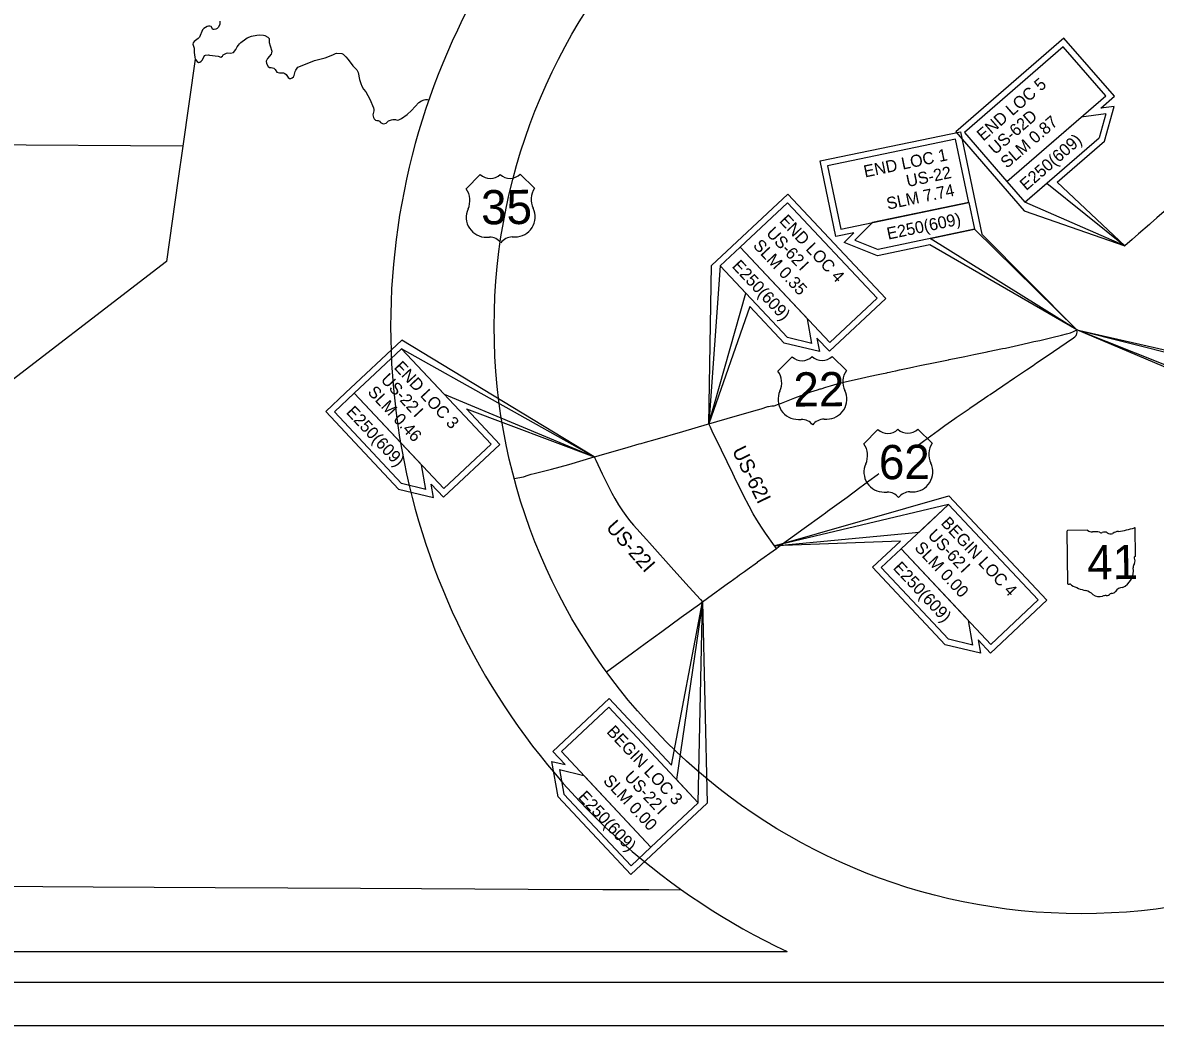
# Model space of a CAD drawing. Extents: x 86259 to 205259, y 423331 to 500331.
# Drawn here: x 126607 to 172720, y 423331 to 464136 of the extents above; entities that cross this region are included whole.
import ezdxf

# ---------------------------------------------------------------- set-up
doc = ezdxf.new("R2010")
doc.units = 0
for name, color, linetype in [('Default', 7, 'Continuous'), ('MT_X_Cells', 7, 'Continuous'), ('PM_P_Cells', 7, 'Continuous'), ('PM_X_Cells', 7, 'Continuous'), ('SC_Scratch1', 7, 'Continuous'), ('SH_Border', 7, 'Continuous'), ('SH_Cut_Line', 7, 'Continuous'), ('SH_Data', 7, 'Continuous'), ('SN_P_Signs', 7, 'Continuous'), ('XS_P_Annotation', 7, 'Continuous')]:
    doc.layers.add(name, color=color, linetype=linetype)

msp = doc.modelspace()

# ---------------------------------------------------------------- linework, layer by layer
at = {"layer": 'MT_X_Cells'}
msp.add_line((146621, 445580), (146999, 445652), dxfattribs=at)
at = {"layer": 'PM_P_Cells'}
for points in [[(174416, 457630), (173884, 457161), (173467, 456791), (173222, 456574), (172987, 456373), (172774, 456190), (172520, 455957), (172483, 455922), (172034, 455537), (171782, 455312), (171481, 455055)], [(166622, 450896), (167153, 451014), (167556, 451104), (167663, 451128), (167776, 451154), (168014, 451208), (168511, 451323), (168904, 451414), (169107, 451473), (169260, 451517), (169383, 451563), (169524, 451634)], [(167478, 450009), (167740, 450187), (167886, 450287), (168311, 450575), (169083, 451105), (169386, 451314), (169443, 451357), (169491, 451399), (169515, 451441), (169525, 451476), (169534, 451549), (169524, 451634)], [(162010, 449940), (162158, 449972), (162304, 450003), (162504, 450047), (162710, 450091), (162890, 450130), (163127, 450179), (163755, 450310), (164296, 450420), (164332, 450428), (164957, 450555), (165327, 450630), (165868, 450741), (165916, 450750), (166497, 450869), (166622, 450896)], [(158697, 449107), (158971, 449197), (159072, 449229), (159110, 449241), (159306, 449299), (159488, 449352), (159770, 449434), (160150, 449531), (160579, 449630), (161105, 449746), (161429, 449817), (161644, 449864)], [(161644, 449864), (161721, 449878)], [(161721, 449878), (161785, 449891), (161818, 449898), (161890, 449914)], [(161890, 449914), (162010, 449940)], [(165770, 448853), (165903, 448944), (165991, 449003), (166517, 449356), (166992, 449679), (167478, 450009)], [(157197, 448545), (157374, 448614), (157494, 448656), (158048, 448874), (158553, 449059), (158697, 449107)], [(162963, 446872), (163283, 447100), (163878, 447538), (164156, 447736), (164561, 448024), (164616, 448061), (165134, 448417), (165171, 448442), (165770, 448853)], [(146999, 445652), (147189, 445726), (147302, 445760), (147434, 445793), (147753, 445865), (148136, 445962), (148848, 446161), (149877, 446461), (149948, 446481), (150078, 446519), (151262, 446862), (151709, 446990), (151783, 447011), (151960, 447062), (152352, 447173), (153488, 447504), (154485, 447791), (154545, 447809), (155619, 448119), (156519, 448378), (156674, 448427), (156937, 448511), (156976, 448522), (157035, 448532), (157103, 448539), (157197, 448545)], [(157297, 442742), (157220, 442848), (156846, 443365), (156682, 443609), (156497, 443899), (156347, 444153), (156181, 444454), (155958, 444892), (155591, 445641), (155520, 445786), (154823, 447212), (154710, 447449), (154603, 447677), (154569, 447750), (154545, 447809)], [(149877, 446461), (149908, 446390), (149939, 446325), (150197, 445778), (150414, 445336), (150593, 444987), (150712, 444772), (150864, 444520), (151025, 444273), (151167, 444073), (151317, 443879), (151475, 443691), (152000, 443097), (152123, 442961), (153117, 441861), (153743, 441168), (154203, 440655), (154284, 440566)], [(160691, 445219), (160834, 445326), (161062, 445492), (161401, 445739), (161461, 445782)], [(159139, 444076), (159285, 444182), (159379, 444251), (159852, 444599), (160169, 444830), (160691, 445219)], [(156526, 442189), (157297, 442742), (157396, 442814), (158428, 443560), (159139, 444076)], [(155704, 441598), (155788, 441659), (155995, 441807), (156099, 441883), (156522, 442186), (156526, 442189)], [(154155, 440473), (154284, 440566), (154494, 440718), (155344, 441339)], [(155344, 441339), (155407, 441384), (155704, 441598)], [(150373, 437719), (151436, 438493), (151950, 438871), (152626, 439361), (153420, 439940), (154155, 440473)]]:
    msp.add_lwpolyline(points, dxfattribs=at)
at = {"layer": 'PM_X_Cells'}
for points in [[(134628, 464197), (134638, 464131), (134632, 464079), (134583, 463955), (134519, 463905), (134469, 463877), (134401, 463859), (134351, 463863), (134277, 463976), (134221, 463990), (134171, 463996), (134117, 463980), (134044, 463944), (133986, 463900), (133932, 463843), (133803, 463550), (133746, 463486), (133588, 463369), (133551, 463317), (133541, 463263), (133587, 463092), (133594, 462978), (133590, 462922), (133612, 462734), (133632, 462657), (133130, 459110), (124610, 459164)], [(133632, 462657), (133709, 462549), (133765, 462517), (133822, 462525), (133876, 462567), (133926, 462618), (134003, 462795), (134055, 462816), (134167, 462826), (134219, 462812), (134568, 462767), (134676, 462736), (134740, 462772), (134774, 462824), (134907, 462898), (134957, 462908), (135063, 462891), (135193, 462923), (135290, 463041), (135344, 463153), (135391, 463221), (135433, 463279), (135483, 463323), (135686, 463478), (135746, 463512), (135919, 463584), (136139, 463633), (136264, 463643), (136406, 463628), (136464, 463612), (136586, 463544), (136636, 463491), (136649, 463323), (136677, 463197), (136745, 462980), (136742, 462912), (136722, 462852), (136577, 462678), (136543, 462626), (136525, 462570), (136539, 462470), (136602, 462358), (136656, 462317), (136721, 462313), (136837, 462279), (136889, 462230), (136950, 462122), (137006, 462102), (137067, 462092), (137121, 462095), (137171, 462099), (137227, 462089), (137279, 462069), (137335, 462023), (137419, 461904), (137473, 461868), (137523, 461870), (137579, 461890), (137629, 461934), (137661, 461988), (137700, 462150), (137726, 462208), (137815, 462324), (138324, 462532), (138491, 462592), (138920, 462707), (139233, 462828), (139337, 462878), (139388, 462892), (139598, 462875), (139652, 462851), (139764, 462752), (139860, 462640), (140053, 462375), (140205, 462210), (140241, 462156), (140263, 462106), (140320, 461823), (140372, 461663), (140420, 461546), (140487, 461436), (140573, 461321), (140741, 461018), (140888, 460665), (140904, 460605), (140903, 460553), (140867, 460391), (140873, 460333), (140889, 460281), (140916, 460228), (140970, 460174), (141024, 460158), (141083, 460156), (141135, 460131), (141175, 460075), (141231, 460041), (141289, 460025), (141345, 460027), (141405, 460046), (141507, 460138), (141618, 460182), (141676, 460190), (141780, 460190), (141848, 460163), (141920, 460185), (142027, 460235), (142264, 460404), (142432, 460556), (142736, 460884), (142842, 460956), (142957, 460997), (143009, 461005), (143069, 461003), (143139, 460982)], [(133130, 459110), (132930, 457697), (132466, 454415), (124754, 448504)], [(153447, 428834), (152105, 428841), (150230, 428850), (147184, 428866), (142841, 428889), (140363, 428903), (134438, 428933), (129473, 428959), (123335, 428991)]]:
    msp.add_lwpolyline(points, dxfattribs=at)
at = {"layer": 'SC_Scratch1'}
for p, q in [((168995, 463509), (164592, 459687)), ((171053, 461138), (168995, 463509)), ((170494, 460652), (171053, 461138)), ((171047, 460727), (170494, 460652)), ((170648, 459313), (171047, 460727)), ((159075, 458507), (164782, 459696)), ((164592, 459687), (167380, 456476)), ((164782, 459696), (165650, 455533)), ((168729, 457647), (170648, 459313)), ((159715, 455433), (159075, 458507)), ((171481, 455055), (168729, 457647)), ((154652, 454255), (157755, 457163)), ((157755, 457163), (161742, 452910)), ((167380, 456476), (171481, 455055)), ((160440, 455584), (159715, 455433)), ((160046, 455189), (160440, 455584)), ((161412, 454650), (160046, 455189)), ((165650, 455533), (169524, 451634)), ((163540, 455093), (161412, 454650)), ((169524, 451634), (163540, 455093)), ((154545, 447809), (154652, 454255)), ((161742, 452910), (159451, 450763)), ((156215, 452588), (154545, 447809)), ((157613, 451097), (156215, 452588)), ((169524, 451634), (177634, 449784)), ((177634, 448192), (169524, 451634)), ((142045, 451220), (139755, 449073)), ((149877, 446461), (142045, 451220)), ((159041, 450753), (157613, 451097)), ((159451, 450763), (158945, 451303)), ((158945, 451303), (159041, 450753)), ((139755, 449073), (138943, 448312)), ((138943, 448312), (141903, 445154)), ((146033, 446967), (144671, 448420)), ((144671, 448420), (149877, 446461)), ((143742, 444820), (146033, 446967)), ((141903, 445154), (143331, 444810)), ((143331, 444810), (143236, 445360)), ((143236, 445360), (143742, 444820)), ((157220, 442848), (164311, 444883)), ((164311, 444883), (168298, 440630)), ((162342, 443038), (157220, 442848)), ((161208, 441975), (162342, 443038)), ((164169, 438817), (161208, 441975)), ((153023, 433916), (154284, 440566)), ((154284, 440566), (154467, 432376)), ((168298, 440630), (166007, 438483)), ((166007, 438483), (165501, 439023)), ((165501, 439023), (165596, 438473)), ((165596, 438473), (164169, 438817)), ((148188, 434481), (150479, 436629)), ((150479, 436629), (153023, 433916)), ((148695, 433941), (148188, 434481)), ((148404, 432625), (148153, 434072)), ((148153, 434072), (148695, 433941)), ((151364, 429467), (148404, 432625)), ((154467, 432376), (151364, 429467)), ((93135, 426333), (157733, 426333))]:
    msp.add_line(p, q, dxfattribs=at)
msp.add_lwpolyline([(157733, 477217), (157733, 497437), (93135, 497437), (93135, 426333), (157733, 426333)], dxfattribs=at)
msp.add_lwpolyline([(157733, 477217), (157733, 497437), (93135, 497437), (93135, 426333), (157733, 426333)], dxfattribs=at)
msp.add_arc((169707, 451775), 28119, 115.2046, 244.7954, dxfattribs=at)
msp.add_arc((169707, 451775), 28119, 115.2046, 244.7954, dxfattribs=at)
at = {"layer": 'SH_Border'}
msp.add_lwpolyline([(91509, 498581), (203509, 498581), (203509, 425081), (91509, 425081)], close=True, dxfattribs=at)
msp.add_circle((169707, 451775), 23903, dxfattribs=at)
at = {"layer": 'SH_Cut_Line'}
msp.add_lwpolyline([(86259, 423331), (205259, 423331), (205259, 500331), (86259, 500331)], close=True, dxfattribs=at)
at = {"layer": 'SH_Data'}
for p, q in [((166676, 457668), (169699, 460293)), ((170703, 460428), (169699, 460293)), ((170703, 460428), (170428, 459453)), ((167405, 456828), (170428, 459453)), ((166676, 457668), (167405, 456828)), ((165127, 456816), (161208, 455999)), ((165127, 456816), (165354, 455727)), ((160492, 455282), (161208, 455999)), ((165354, 455727), (161435, 454910)), ((160492, 455282), (161435, 454910)), ((155817, 455004), (155006, 454243)), ((155817, 455004), (158555, 452084)), ((155006, 454243), (157744, 451323)), ((158729, 451085), (158555, 452084)), ((158729, 451085), (157744, 451323)), ((140108, 449061), (139296, 448300)), ((140108, 449061), (142846, 446141)), ((139296, 448300), (142035, 445380)), ((143020, 445142), (142846, 446141)), ((143020, 445142), (142035, 445380)), ((162373, 442724), (161562, 441963)), ((162373, 442724), (165111, 439804)), ((161562, 441963), (164300, 439043)), ((165285, 438806), (165111, 439804)), ((165285, 438806), (164300, 439043)), ((148464, 433739), (149449, 433502)), ((148464, 433739), (148638, 432741)), ((152187, 430582), (149449, 433502)), ((151376, 429821), (148638, 432741)), ((152187, 430582), (151376, 429821))]:
    msp.add_line(p, q, dxfattribs=at)
for points in [[(166676, 457668), (170700, 461163), (168970, 463156), (164945, 459662)], [(164588, 459400), (159370, 458313), (159909, 455728), (165127, 456816)], [(168298, 457604), (171481, 455055), (167405, 456828)], [(159463, 451116), (155817, 455004), (157743, 456810), (161389, 452922)], [(165354, 455727), (169524, 451634), (163556, 455352)], [(155006, 454243), (154545, 447809), (156054, 453126)], [(177884, 448308), (169524, 451634), (177884, 449534)], [(140108, 449061), (143754, 445173), (145679, 446979), (142034, 450867)], [(143765, 449021), (149877, 446461), (142034, 450867)], [(164299, 444530), (157220, 442848), (163099, 443405)], [(164299, 444530), (167945, 440642), (166019, 438836), (162373, 442724)], [(154113, 432387), (154284, 440566), (153229, 433330)], [(154113, 432387), (150468, 436276), (148542, 434470), (152187, 430582)]]:
    msp.add_lwpolyline(points, close=True, dxfattribs=at)
at = {"layer": 'SN_P_Signs'}
for p, q in [((145239, 457955), (144664, 457369)), ((147448, 457395), (146863, 457970)), ((145495, 455405), (145611, 455406)), ((146539, 455414), (146655, 455415)), ((157932, 450541), (157357, 449956)), ((160141, 449982), (159556, 450556)), ((158188, 447991), (158304, 447992)), ((159232, 448001), (159348, 448002)), ((161428, 447582), (160854, 446996)), ((163638, 447023), (163052, 447597)), ((161684, 445032), (161800, 445033)), ((162728, 445042), (162844, 445043))]:
    msp.add_line(p, q, dxfattribs=at)
for centre, radius, start, end in [((145641, 458373), 580, 226.1115, 314.9656), ((146453, 458380), 580, 226.1115, 314.9656), ((144003, 456897), 812, 335.0857, 35.5395), ((148118, 456936), 812, 145.5376, 205.9914), ((145478, 456216), 812, 155.3705, 271.1768), ((146656, 456228), 812, 269.9003, 25.7066), ((145616, 454826), 580, 37.4084, 90.5385), ((146544, 454834), 580, 90.5385, 143.6686), ((158334, 450959), 580, 226.1115, 314.9656), ((159146, 450967), 580, 226.1115, 314.9656), ((156696, 449484), 812, 335.0857, 35.5395), ((160811, 449522), 812, 145.5376, 205.9914), ((158171, 448803), 812, 155.3705, 271.1768), ((159349, 448814), 812, 269.9003, 25.7066), ((158309, 447412), 580, 37.4084, 90.5385), ((159237, 447421), 580, 90.5385, 143.6686), ((161830, 448000), 580, 226.1115, 314.9656), ((162642, 448008), 580, 226.1115, 314.9656), ((160193, 446524), 812, 335.0857, 35.5395), ((164307, 446563), 812, 145.5376, 205.9914), ((161668, 445844), 812, 155.3705, 271.1768), ((162846, 445855), 812, 269.9003, 25.7066), ((161806, 444453), 580, 37.4084, 90.5385), ((162734, 444462), 580, 90.5385, 143.6686)]:
    msp.add_arc(centre, radius, start, end, dxfattribs=at)
at = {"layer": 'XS_P_Annotation'}
for p, q in [((169120, 443434), (169140, 441321)), ((169963, 443478), (169147, 443470)), ((171914, 442443), (171904, 443549)), ((171914, 442444), (171914, 442443))]:
    msp.add_line(p, q, dxfattribs=at)
for centre, radius, start, end in [((169152, 443439), 32.3, 98.6686, 188.6686), ((170155, 443725), 313, 232.1581, 271.6504), ((170272, 442295), 1123, 81.0252, 95.5268), ((170516, 443462), 90.3, 220.3306, 297.6409), ((170651, 443219), 188, 55.0052, 119.6797), ((170890, 443557), 226, 234.3948, 295.3667), ((171295, 442845), 594, 97.8847, 121.3074), ((170885, 446368), 2953, 276.383, 289.445), ((171873, 443553), 31, 352.4006, 98.2765), ((171908, 442362), 48, 108.4825, 210.8755), ((171604, 442219), 288, 340.5715, 24.1881), ((171881, 442439), 33.2, 290.1424, 8.2727), ((171093, 441832), 739, 292.8474, 9.5244), ((172029, 441982), 210, 137.345, 187.4681), ((169172, 441316), 32.5, 172.4969, 258.8452), ((169175, 441533), 248, 267.8775, 281.1424), ((169229, 441200), 89.5, 30.2869, 93.8103), ((170342, 443109), 2132, 240.9515, 257.737), ((169732, 440377), 667, 47.7227, 76.3745), ((170446, 441200), 423, 231.2389, 286.8304), ((170723, 441045), 226, 269.3156, 316.0878), ((170929, 440842), 63.5, 66.2903, 133.187), ((170899, 441132), 239, 283.4117, 323.8157), ((171415, 440749), 404, 94.9417, 143.1153), ((170697, 440472), 348, 86.2337, 111.7485)]:
    msp.add_arc(centre, radius, start, end, dxfattribs=at)

# ---------------------------------------------------------------- texts
at = {"layer": 'Default'}
for s, rotation, p in [('END LOC 5', 40.9628, (165713, 459293)), ('US-62D', 40.9628, (166195, 458738)), ('SLM 0.87', 40.9628, (166677, 458183)), ('E250(609)', 40.9628, (167463, 457278)), ('END LOC 1', 11.7719, (160901, 457833)), ('US-22', 11.7719, (162634, 457443)), ('SLM 7.74', 11.7719, (161828, 456524)), ('END LOC 4', 313.1551, (157385, 456047)), ('E250(609)', 11.7719, (161842, 455303)), ('US-62', 313.1551, (156849, 455544)), ('SLM 0.35', 313.1551, (156313, 455042)), ('E250(609)', 313.1551, (155457, 454203)), ('I', 313.1551, (158176, 454129)), ('END LOC 3', 313.1551, (141694, 450085)), ('US-22', 313.1551, (141158, 449582)), ('SLM 0.46', 313.1551, (140622, 449079)), ('E250(609)', 313.1551, (139748, 448260)), ('I', 313.1551, (142485, 448167)), ('BEGIN LOC 4', 313.1551, (163960, 443748)), ('US-62', 313.1551, (163423, 443245)), ('SLM 0.00', 313.1551, (162887, 442743)), ('E250(609)', 313.1551, (162013, 441923)), ('I', 313.1551, (164750, 441830)), ('BEGIN LOC 3', 313.1551, (150350, 435257)), ('SLM 0.00', 313.1551, (150210, 433257)), ('US-22', 313.1551, (151070, 433414)), ('E250(609)', 313.1551, (149185, 432598)), ('I', 313.1551, (152397, 431999))]:
    msp.add_text(s, height=490, rotation=rotation, dxfattribs=at).set_placement(p)
at = {"layer": 'SH_Data'}
for s, rotation, p in [('US-62I', 296.0882, (155474, 446726)), ('US-22I', 311.4895, (150326, 443569))]:
    msp.add_text(s, height=595, rotation=rotation, dxfattribs=at).set_placement(p)
at = {"layer": 'SN_P_Signs'}
for s, p in [('35', (145277, 455925)), ('22', (157992, 448511)), ('62', (161471, 445552))]:
    msp.add_text(s, height=1392.2, rotation=0.5385, dxfattribs=at).set_placement(p)
at = {"layer": 'XS_P_Annotation'}
msp.add_text('41', height=1392.2, rotation=0.5385, dxfattribs=at).set_placement((169953, 441477))

doc.saveas('drawing.dxf')
